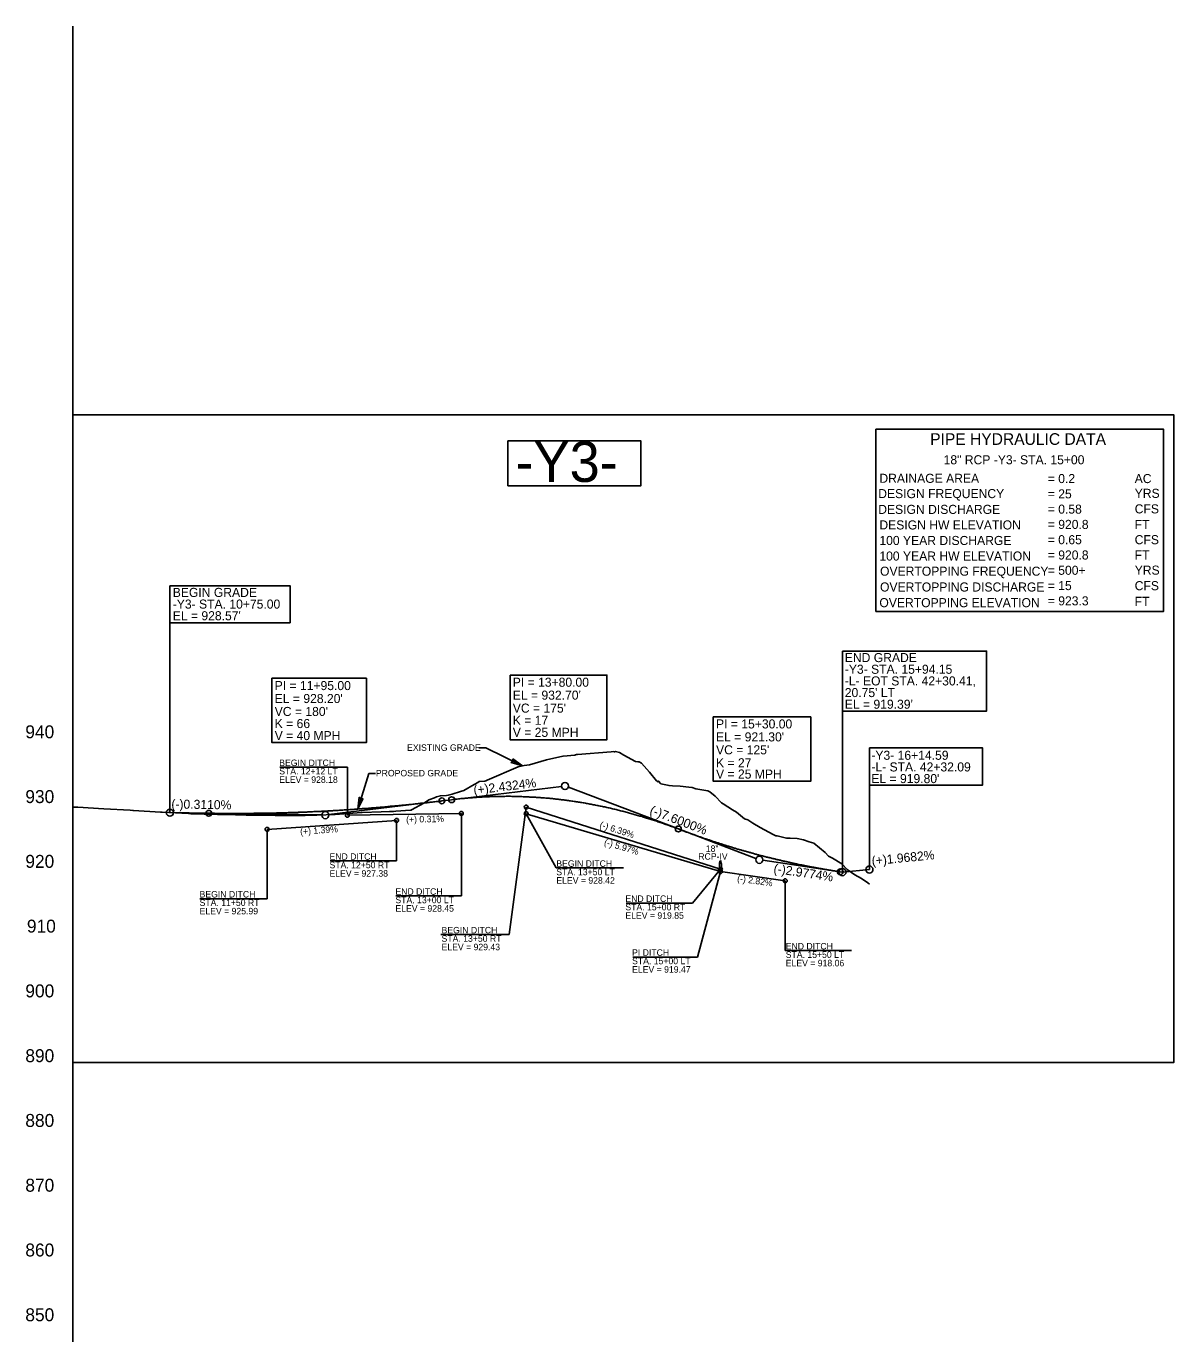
# Model space of a CAD drawing. Extents: x 1968019 to 1983409, y 545058 to 567558.
# Drawn here: x 1971705 to 1972591, y 550549 to 551558 of the extents above; entities that cross this region are included whole.
import ezdxf

# ---------------------------------------------------------------- set-up
doc = ezdxf.new("R2010")
doc.units = 0
for name, color, linetype in [('Exist Profile Cell', 7, 'Continuous'), ('Exist Vertical Profile Ground Line', 7, 'Continuous'), ('Exist Vertical Profile Vertical Axis Label', 7, 'Continuous'), ('Old_Level_1', 7, 'Continuous'), ('Old_Level_20', 7, 'Continuous'), ('Prop Drainage Structure Pipe RCP 18in Class III', 7, 'Continuous'), ('Prop Grid Mask', 7, 'Continuous'), ('Prop Terminator CELL', 7, 'Continuous'), ('Prop Vertical Profile Curve Label', 7, 'Continuous'), ('Prop Vertical Profile Ditch Grade Left', 7, 'Continuous'), ('Prop Vertical Profile Ditch Grade Left Label', 7, 'Continuous'), ('Prop Vertical Profile Ditch Grade Right', 7, 'Continuous'), ('Prop Vertical Profile Ditch Grade Right Label', 7, 'Continuous'), ('Prop Vertical Profile Grade', 7, 'Continuous'), ('Prop Vertical Profile Grade Label', 7, 'Continuous'), ('Prop VPI Label', 7, 'Continuous'), ('Scratch_Level_8', 7, 'Continuous'), ('Sheet Data Text CELL', 7, 'Continuous')]:
    doc.layers.add(name, color=color, linetype=linetype)

msp = doc.modelspace()

# ---------------------------------------------------------------- linework, layer by layer
at = {"layer": 'Exist Profile Cell'}
msp.add_line((1971741.4, 550308.4), (1971741.4, 551558.4), dxfattribs=at)
at = {"layer": 'Exist Vertical Profile Ground Line'}
for points in [[(1971741.4, 550954.3), (1971741.6, 550955.6), (1971745.3, 550955.5), (1971765.3, 550954.3), (1971785.6, 550953.1), (1971787.9, 550952.9), (1971788.3, 550952.9), (1971809.1, 550951.6), (1971810.4, 550951.6), (1971830.8, 550950.6), (1971831.5, 550950.6), (1971832.5, 550950.5), (1971853.1, 550949.9), (1971867.1, 550949.6), (1971867.9, 550949.6), (1971875.2, 550949.4), (1971875.4, 550949.4), (1971885.5, 550949.3), (1971897.7, 550949), (1971899.1, 550949), (1971920.8, 550949), (1971929.7, 550949.4), (1971943.9, 550949.8), (1971964.3, 550951.3), (1971964.5, 550951.3), (1971964.7, 550951.3), (1971979.6, 550951.9), (1971985.9, 550952.2), (1971989.1, 550952.2), (1971990.7, 550952.4), (1972002.2, 550953.3), (1972002.8, 550953.3), (1972002.9, 550953.4), (1972012.5, 550958.7), (1972014.5, 550959.9), (1972016.2, 550961.1), (1972020.7, 550962.7), (1972022.3, 550963.5), (1972025.2, 550964.4), (1972030, 550964.5), (1972031.3, 550964.7), (1972034.2, 550965.5), (1972040.7, 550967.6), (1972043.3, 550968.4), (1972051.4, 550973.1), (1972054, 550974.5), (1972055.2, 550975.3), (1972059.4, 550975.7), (1972060.3, 550975.9), (1972060.3, 550975.9), (1972060.3, 550975.9), (1972061.3, 550976.3), (1972085.2, 550986.6), (1972088.6, 550987.5), (1972090, 550987.8), (1972093.9, 550988.3), (1972107, 550992), (1972119.7, 550994.9), (1972120.1, 550994.9), (1972129.1, 550995.7), (1972129.5, 550995.9), (1972130.3, 550996.1), (1972131, 550996.1), (1972157.1, 550998.3), (1972158.6, 550998.4), (1972159.6, 550998.2), (1972160.5, 550998.5), (1972163.6, 550997.7), (1972166.9, 550995.7), (1972175.8, 550990.9), (1972177.6, 550990.6), (1972178.7, 550990.5), (1972180.4, 550989.4), (1972182.5, 550987.1), (1972186.6, 550982.6), (1972192, 550975.9), (1972193.2, 550975), (1972193.6, 550975.7), (1972195.5, 550973.6), (1972201.8, 550972.2), (1972204.3, 550972), (1972210.2, 550971.7), (1972217.1, 550970.9), (1972219.7, 550970.6), (1972222.5, 550969.8), (1972231.7, 550968.1), (1972233.1, 550967.3), (1972237.2, 550964.1), (1972242.3, 550958.9), (1972243.4, 550958.1), (1972250.8, 550953.4), (1972253.8, 550951.6), (1972259.9, 550946.4), (1972262.5, 550945.8), (1972266.3, 550943.2), (1972272, 550939.9), (1972282, 550934.4), (1972284.2, 550933.5), (1972285.3, 550933.3), (1972292.4, 550931.6), (1972295.1, 550931.7)], [(1972295.1, 550931.7), (1972300.6, 550931.4), (1972305.6, 550930.4), (1972310, 550928.7), (1972313.5, 550927.8), (1972322.3, 550920.5), (1972324.7, 550917.8), (1972327.8, 550916.2), (1972335.2, 550911.9), (1972339.2, 550907.4), (1972345.2, 550903.4), (1972350.2, 550900.4), (1972355.3, 550897.1), (1972356.4, 550896)]]:
    msp.add_lwpolyline(points, dxfattribs=at)
at = {"layer": 'Old_Level_20'}
for p, q in [((1972055, 551001.4), (1972060.2, 551001.4)), ((1972060.2, 551001.4), (1972088.6, 550987.5)), ((1971961.5, 550954.1), (1971970, 550981.6)), ((1971970, 550981.6), (1971975.2, 550981.6))]:
    msp.add_line(p, q, dxfattribs=at)
at = {"layer": 'Prop Drainage Structure Pipe RCP 18in Class III'}
for major_axis in [(0, 3.75), (0, -3.75)]:
    msp.add_ellipse((1972241.4, 550910.5), major_axis=major_axis, ratio=0.2, start_param=0, end_param=3.141593, dxfattribs=at)
at = {"layer": 'Prop Grid Mask'}
for p, q in [((1971816.4, 550951.3), (1971816.4, 551097.9)), ((1972335.6, 550905.4), (1972335.6, 551029.7)), ((1972356.4, 550907.4), (1972356.4, 550972.5))]:
    msp.add_line(p, q, dxfattribs=at)
for points in [[(1972361.4, 551247.3), (1972583.5, 551247.3), (1972583.5, 551106.6), (1972361.4, 551106.6)], [(1972077.4, 551238.2), (1972180, 551238.2), (1972180, 551203.7), (1972077.4, 551203.7)], [(1971816.4, 551126.4), (1971909.2, 551126.4), (1971909.2, 551097.9), (1971816.4, 551097.9)], [(1972335.6, 551076), (1972446.8, 551076), (1972446.8, 551029.7), (1972335.6, 551029.7)], [(1971895.1, 551055.1), (1971968.1, 551055.1), (1971968.1, 551005.4), (1971895.1, 551005.4)], [(1972079, 551057.5), (1972153.8, 551057.5), (1972153.8, 551007.6), (1972079, 551007.6)], [(1972235.9, 551025.2), (1972311.1, 551025.2), (1972311.1, 550975.6), (1972235.9, 550975.6)], [(1972356.4, 551001.4), (1972443.6, 551001.4), (1972443.6, 550972.5), (1972356.4, 550972.5)]]:
    msp.add_lwpolyline(points, close=True, dxfattribs=at)
at = {"layer": 'Prop Terminator CELL'}
for points in [[(1972081.2, 550992.8), (1972088.6, 550987.5), (1972079.8, 550990), (1972081.5, 550991)], [(1971965.6, 550962.2), (1971961.5, 550954.1), (1971962.6, 550963.2), (1971963.8, 550961.6)]]:
    msp.add_lwpolyline(points, close=True, dxfattribs=at)
at = {"layer": 'Prop Vertical Profile Curve Label'}
for centre in [(1972026.4, 550960.4), (1972033.9, 550961.3), (1971846.4, 550950.8), (1972208.9, 550938.7), (1972333.9, 550905.6)]:
    msp.add_circle(centre, 2.25, dxfattribs=at)
at = {"layer": 'Prop Vertical Profile Ditch Grade Left'}
msp.add_line((1971953.4, 550949.3), (1972041.4, 550950.7), dxfattribs=at)
msp.add_lwpolyline([(1972091.4, 550950.5), (1972241.4, 550905.8), (1972291.4, 550898.7)], dxfattribs=at)
at = {"layer": 'Prop Vertical Profile Ditch Grade Left Label'}
for p, q in [((1971953.4, 550986.3), (1971901.2, 550986.3)), ((1971953.4, 550949.3), (1971953.4, 550986.3)), ((1972041.4, 550950.7), (1972041.4, 550887)), ((1972091.4, 550950.5), (1972114.5, 550908.6)), ((1972166.5, 550908.6), (1972114.5, 550908.6)), ((1972241.4, 550905.8), (1972223.6, 550839.8)), ((1972291.4, 550898.7), (1972291.4, 550844.8)), ((1972041.4, 550887), (1971990.8, 550887)), ((1972342.7, 550844.8), (1972291.4, 550844.8)), ((1972223.6, 550839.8), (1972173.7, 550839.8))]:
    msp.add_line(p, q, dxfattribs=at)
for centre in [(1972041.4, 550950.7), (1971953.4, 550949.3), (1972091.4, 550950.5), (1972241.4, 550905.8), (1972291.4, 550898.7)]:
    msp.add_circle(centre, 1.5, dxfattribs=at)
at = {"layer": 'Prop Vertical Profile Ditch Grade Right'}
for p, q in [((1972091.4, 550955.6), (1972241.4, 550907.7)), ((1971891.4, 550938.4), (1971991.4, 550945.3))]:
    msp.add_line(p, q, dxfattribs=at)
at = {"layer": 'Prop Vertical Profile Ditch Grade Right Label'}
for p, q in [((1972091.4, 550955.6), (1972078.4, 550857.2)), ((1971991.4, 550945.3), (1971991.4, 550914)), ((1971891.4, 550938.4), (1971891.4, 550884.8)), ((1971991.4, 550914), (1971940, 550914)), ((1972241.4, 550907.7), (1972219.8, 550881.5)), ((1971891.4, 550884.8), (1971839.4, 550884.8)), ((1972219.8, 550881.5), (1972168.5, 550881.5)), ((1972078.4, 550857.2), (1972025.6, 550857.2))]:
    msp.add_line(p, q, dxfattribs=at)
for centre in [(1972091.4, 550955.6), (1971991.4, 550945.3), (1971891.4, 550938.4), (1972241.4, 550907.7)]:
    msp.add_circle(centre, 1.5, dxfattribs=at)
at = {"layer": 'Prop Vertical Profile Grade'}
for p, q in [((1972026.4, 550960.4), (1972033.9, 550961.3)), ((1971816.4, 550951.3), (1971846.4, 550950.8)), ((1972333.9, 550905.6), (1972335.6, 550905.4)), ((1972335.6, 550905.4), (1972356.4, 550907.4))]:
    msp.add_line(p, q, dxfattribs=at)
for points in [[(1972033.9, 550961.3), (1972037.4, 550961.7), (1972040.9, 550962.1), (1972044.4, 550962.4), (1972047.9, 550962.7), (1972051.4, 550963), (1972054.9, 550963.2), (1972058.4, 550963.4), (1972061.9, 550963.6), (1972065.4, 550963.7), (1972068.9, 550963.8), (1972072.4, 550963.8), (1972075.9, 550963.9), (1972079.4, 550963.9), (1972082.9, 550963.8), (1972086.4, 550963.7), (1972089.9, 550963.6), (1972093.4, 550963.4), (1972096.9, 550963.3), (1972100.4, 550963), (1972103.9, 550962.8), (1972107.4, 550962.5), (1972110.9, 550962.2), (1972114.4, 550961.8), (1972117.9, 550961.4), (1972121.4, 550961), (1972124.9, 550960.5), (1972128.4, 550960), (1972131.9, 550959.4), (1972135.4, 550958.9), (1972138.9, 550958.3), (1972142.4, 550957.6), (1972145.9, 550956.9), (1972149.4, 550956.2), (1972152.9, 550955.5), (1972156.4, 550954.7), (1972159.9, 550953.9), (1972163.4, 550953), (1972166.9, 550952.1), (1972170.4, 550951.2), (1972173.9, 550950.2), (1972177.4, 550949.2), (1972180.9, 550948.2), (1972184.4, 550947.1), (1972187.9, 550946), (1972191.4, 550944.9), (1972194.9, 550943.7), (1972198.4, 550942.5), (1972201.9, 550941.3), (1972205.4, 550940), (1972208.9, 550938.7)], [(1971846.4, 550950.8), (1971850, 550950.8), (1971853.6, 550950.7), (1971857.2, 550950.7), (1971860.8, 550950.7), (1971864.4, 550950.7), (1971868, 550950.7), (1971871.6, 550950.7), (1971875.2, 550950.7), (1971878.8, 550950.7), (1971882.4, 550950.8), (1971886, 550950.8), (1971889.6, 550950.9), (1971893.2, 550950.9), (1971896.8, 550951), (1971900.4, 550951.1), (1971904, 550951.2), (1971907.6, 550951.3), (1971911.2, 550951.4), (1971914.8, 550951.5), (1971918.4, 550951.7), (1971922, 550951.8), (1971925.6, 550952), (1971929.2, 550952.2), (1971932.8, 550952.3), (1971936.4, 550952.5), (1971940, 550952.7), (1971943.6, 550952.9), (1971947.2, 550953.1), (1971950.8, 550953.4), (1971954.4, 550953.6), (1971958, 550953.8), (1971961.6, 550954.1), (1971965.2, 550954.4), (1971968.8, 550954.6), (1971972.4, 550954.9), (1971976, 550955.2), (1971979.6, 550955.5), (1971983.2, 550955.8), (1971986.8, 550956.2), (1971990.4, 550956.5), (1971994, 550956.8), (1971997.6, 550957.2), (1972001.2, 550957.5), (1972004.8, 550957.9), (1972008.4, 550958.3), (1972012, 550958.7), (1972015.6, 550959.1), (1972019.2, 550959.5), (1972022.8, 550959.9), (1972026.4, 550960.4)], [(1972208.9, 550938.7), (1972211.4, 550937.7), (1972213.9, 550936.8), (1972216.4, 550935.9), (1972218.9, 550935), (1972221.4, 550934.1), (1972223.9, 550933.2), (1972226.4, 550932.3), (1972228.9, 550931.4), (1972231.4, 550930.6), (1972233.9, 550929.8), (1972236.4, 550928.9), (1972238.9, 550928.1), (1972241.4, 550927.3), (1972243.9, 550926.5), (1972246.4, 550925.7), (1972248.9, 550925), (1972251.4, 550924.2), (1972253.9, 550923.4), (1972256.4, 550922.7), (1972258.9, 550922), (1972261.4, 550921.3), (1972263.9, 550920.6), (1972266.4, 550919.9), (1972268.9, 550919.2), (1972271.4, 550918.5), (1972273.9, 550917.9), (1972276.4, 550917.2), (1972278.9, 550916.6), (1972281.4, 550916), (1972283.9, 550915.4), (1972286.4, 550914.8), (1972288.9, 550914.2), (1972291.4, 550913.6), (1972293.9, 550913.1), (1972296.4, 550912.5), (1972298.9, 550912), (1972301.4, 550911.4), (1972303.9, 550910.9), (1972306.4, 550910.4), (1972308.9, 550909.9), (1972311.4, 550909.4), (1972313.9, 550909), (1972316.4, 550908.5), (1972318.9, 550908.1), (1972321.4, 550907.6), (1972323.9, 550907.2), (1972326.4, 550906.8), (1972328.9, 550906.4), (1972331.4, 550906), (1972333.9, 550905.6)]]:
    msp.add_spline(points, degree=3, dxfattribs=at)
at = {"layer": 'Prop VPI Label'}
for p, q in [((1972033.9, 550961.3), (1972118.7, 550971.6)), ((1972208.9, 550938.7), (1972124, 550970.9)), ((1972026.4, 550960.4), (1971939.1, 550949.8)), ((1971846.4, 550950.8), (1971933.7, 550949.5)), ((1972208.9, 550938.7), (1972268.8, 550915.9)), ((1972333.9, 550905.6), (1972274.1, 550914.5))]:
    msp.add_line(p, q, dxfattribs=at)
for centre in [(1972121.4, 550971.9), (1971816.4, 550951.3), (1971936.4, 550949.4), (1972271.4, 550914.9), (1972335.6, 550905.4), (1972356.4, 550907.4)]:
    msp.add_circle(centre, 2.75, dxfattribs=at)
at = {"layer": 'Scratch_Level_8'}
msp.add_lwpolyline([(1971741.4, 551258.4), (1972591.4, 551258.4), (1972591.4, 550758.4), (1971741.4, 550758.4)], close=True, dxfattribs=at)
at = {"layer": 'Sheet Data Text CELL'}
msp.add_lwpolyline([(1972361.4, 551106.6), (1972583.5, 551106.6), (1972583.5, 551247.3), (1972361.4, 551247.3)], close=True, dxfattribs=at)

# ---------------------------------------------------------------- texts
at = {"layer": 'Exist Vertical Profile Vertical Axis Label'}
for s, p in [('940', (1971704.8, 551008.7)), ('930', (1971704.8, 550958.7)), ('920', (1971704.8, 550908.7)), ('910', (1971706, 550858.7)), ('900', (1971704.8, 550808.7)), ('890', (1971704.8, 550758.7)), ('880', (1971704.8, 550708.7)), ('870', (1971704.8, 550658.7)), ('860', (1971704.8, 550608.7)), ('850', (1971704.8, 550558.7))]:
    msp.add_text(s, height=10, dxfattribs=at).set_placement(p)
at = {"layer": 'Old_Level_1'}
msp.add_text('-Y3-', height=31.25, dxfattribs=at).set_placement((1972083.2, 551206.6))
at = {"layer": 'Old_Level_20'}
for s, p in [('EXISTING GRADE', (1971999.5, 550999)), ('PROPOSED GRADE', (1971975.4, 550979.3))]:
    msp.add_text(s, height=5, rotation=360, dxfattribs=at).set_placement(p)
at = {"layer": 'Prop Drainage Structure Pipe RCP 18in Class III'}
for s, p in [('18"', (1972230.1, 550921)), ('RCP-IV', (1972224.3, 550915))]:
    msp.add_text(s, height=5, dxfattribs=at).set_placement(p)
at = {"layer": 'Prop Vertical Profile Curve Label'}
for s, p in [("VC = 180'", (1971897.3, 551025.9)), ("VC = 175'", (1972081.1, 551028.5)), ('K = 66', (1971897.3, 551016.6)), ('K = 17', (1972081.1, 551019.1)), ('V = 40 MPH', (1971897.3, 551007.3)), ('V = 25 MPH', (1972081.1, 551009.8)), ("VC = 125'", (1972238, 550996.3)), ('K = 27', (1972238, 550986.3)), ('V = 25 MPH', (1972238, 550977.6))]:
    msp.add_text(s, height=7, dxfattribs=at).set_placement(p)
at = {"layer": 'Prop Vertical Profile Ditch Grade Left Label'}
for s, p in [('STA. 12+12 LT', (1971900.8, 550980.8)), ('BEGIN DITCH', (1971900.8, 550987.3)), ('ELEV = 928.18', (1971900.8, 550974.3)), ('BEGIN DITCH', (1972114.7, 550909.5)), ('STA. 13+50 LT', (1972114.7, 550903)), ('END DITCH', (1971990.5, 550887.9)), ('ELEV = 928.42', (1972114.7, 550896.5)), ('STA. 13+00 LT', (1971990.5, 550881.4)), ('ELEV = 928.45', (1971990.5, 550874.9)), ('PI DITCH', (1972173.2, 550840.8)), ('STA. 15+50 LT', (1972291.8, 550839.2)), ('END DITCH', (1972291.8, 550845.7)), ('STA. 15+00 LT', (1972173.2, 550834.3)), ('ELEV = 919.47', (1972173.2, 550827.8)), ('ELEV = 918.06', (1972291.8, 550832.7))]:
    msp.add_text(s, height=5, dxfattribs=at).set_placement(p)
for s, rotation, p in [('(+) 0.31%', 0.8789, (1971998.8, 550943.6)), ('(-) 5.97%', 343.3884, (1972151.2, 550926.4)), ('(-) 2.82%', 351.9742, (1972254.1, 550898.2))]:
    msp.add_text(s, height=5, rotation=rotation, dxfattribs=at).set_placement(p)
at = {"layer": 'Prop Vertical Profile Ditch Grade Right Label'}
for s, rotation, p in [('(-) 6.39%', 342.29, (1972147.7, 550939.9)), ('(+) 1.39%', 3.9757, (1971917.1, 550934.2))]:
    msp.add_text(s, height=5, rotation=rotation, dxfattribs=at).set_placement(p)
for s, p in [('STA. 12+50 RT', (1971939.6, 550908.4)), ('END DITCH', (1971939.6, 550914.9)), ('ELEV = 927.38', (1971939.6, 550901.9)), ('STA. 11+50 RT', (1971839.3, 550879.3)), ('BEGIN DITCH', (1971839.3, 550885.8)), ('END DITCH', (1972168, 550882.4)), ('ELEV = 925.99', (1971839.3, 550872.8)), ('STA. 15+00 RT', (1972168, 550875.9)), ('ELEV = 919.85', (1972168, 550869.4)), ('BEGIN DITCH', (1972026.1, 550858.1)), ('STA. 13+50 RT', (1972026.1, 550851.6)), ('ELEV = 929.43', (1972026.1, 550845.1))]:
    msp.add_text(s, height=5, dxfattribs=at).set_placement(p)
at = {"layer": 'Prop Vertical Profile Grade Label'}
for s, rotation, p in [('(+)2.4324%', 6.9343, (1972051.2, 550965.2)), ('(-)0.3110%', 359.109, (1971817.5, 550954.5)), ('(-)7.6000%', 339.1932, (1972186.2, 550950.5)), ('(+)1.9682%', 5.6205, (1972358.5, 550910.6)), ('(-)2.9774%', 351.5326, (1972282.1, 550904.9))]:
    msp.add_text(s, height=7, rotation=rotation, dxfattribs=at).set_placement(p)
at = {"layer": 'Prop VPI Label'}
for s, p in [('BEGIN GRADE', (1971818.6, 551117.8)), ('-Y3- STA. 10+75.00 ', (1971818.6, 551108.8)), ("EL = 928.57'", (1971818.6, 551099.8)), ('END GRADE', (1972337.4, 551067.5)), ('-Y3- STA. 15+94.15', (1972337.4, 551058.5)), ('PI = 13+80.00', (1972081.1, 551048.5)), ('-L- EOT STA. 42+30.41,', (1972337.4, 551049.5)), ('PI = 11+95.00', (1971897.3, 551045.9)), ("EL = 928.20'", (1971897.3, 551035.9)), ("EL = 932.70'", (1972081.1, 551038.5)), ("20.75' LT", (1972337.4, 551040.5)), ("EL = 919.39'", (1972337.4, 551031.5)), ('PI = 15+30.00', (1972238, 551016.3)), ("EL = 921.30'", (1972238, 551006.3)), ('-Y3- 16+14.59', (1972357.9, 550992.1)), ('-L- STA. 42+32.09', (1972357.9, 550983.1)), ("EL = 919.80'", (1972357.9, 550974.1))]:
    msp.add_text(s, height=7, dxfattribs=at).set_placement(p)
at = {"layer": 'Sheet Data Text CELL'}
for s, height, p in [('PIPE HYDRAULIC DATA', 9, (1972403.3, 551235.2)), ('18" RCP -Y3- STA. 15+00', 7, (1972413.7, 551220.2)), ('DRAINAGE AREA', 7, (1972364.1, 551205.9)), ('= 0.2', 7, (1972494.1, 551205.7)), ('AC', 7, (1972561.2, 551205.7)), ('DESIGN FREQUENCY', 7, (1972363.2, 551194.1)), ('= 25', 7, (1972494.1, 551193.9)), ('YRS', 7, (1972561.2, 551194.3)), ('DESIGN DISCHARGE', 7, (1972363.2, 551181.9)), ('= 0.58', 7, (1972494.1, 551182.1)), ('CFS', 7, (1972561.2, 551182.3)), ('DESIGN HW ELEVATION', 7, (1972364.1, 551169.9)), ('= 920.8', 7, (1972494.1, 551170.3)), ('FT', 7, (1972561.2, 551170.3)), ('100 YEAR DISCHARGE', 7, (1972364.1, 551157.9)), ('= 0.65', 7, (1972494.1, 551158.5)), ('CFS', 7, (1972561.2, 551158.5)), ('100 YEAR HW ELEVATION', 7, (1972364.1, 551145.9)), ('= 920.8', 7, (1972494.1, 551146.7)), ('FT', 7, (1972561.2, 551146.7)), ('OVERTOPPING FREQUENCY', 7, (1972364.6, 551134.2)), ('= 500+', 7, (1972494.1, 551134.9)), ('YRS', 7, (1972561.2, 551135)), ('OVERTOPPING DISCHARGE', 7, (1972364.6, 551122)), ('= 15', 7, (1972494.1, 551123.1)), ('CFS', 7, (1972561.2, 551123)), ('OVERTOPPING ELEVATION', 7, (1972364.1, 551109.9)), ('= 923.3', 7, (1972494.1, 551111.3)), ('FT', 7, (1972561.2, 551110.9))]:
    msp.add_text(s, height=height, rotation=360, dxfattribs=at).set_placement(p)

doc.saveas('drawing.dxf')
